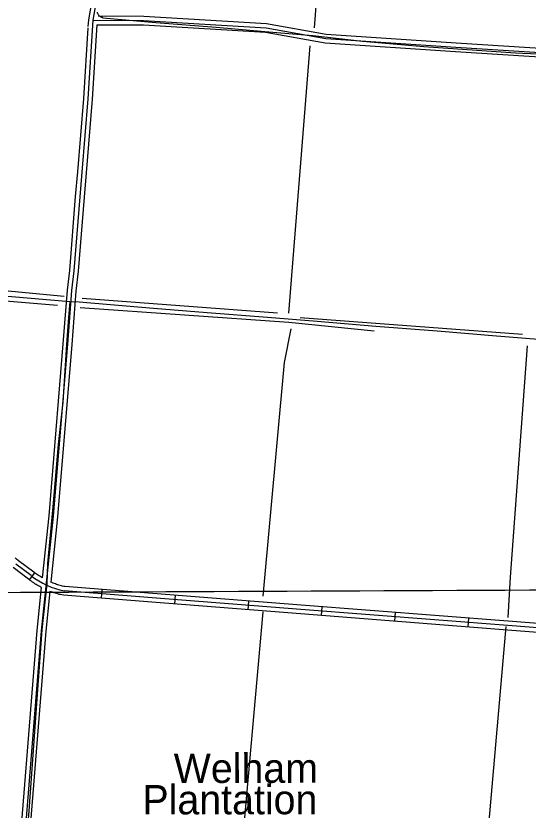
# Model space of a CAD drawing. Extents: x 3419139 to 3457078, y 540382 to 565875.
# Drawn here: x 3450842 to 3452584, y 551211 to 553912 of the extents above; entities that cross this region are included whole.
import ezdxf

# ---------------------------------------------------------------- set-up
doc = ezdxf.new("R2010")
doc.units = 0
for name, color, linetype in [('V-BLDG-IDEN', 7, 'Continuous'), ('V-DTCH-CNTR', 7, 'Continuous'), ('V-GRID-MAJR', 7, 'Continuous'), ('V-RAIL-TRAK', 7, 'Continuous'), ('V-ROAD-CNTR', 7, 'Continuous'), ('V-TOPO-SHOR', 7, 'Continuous')]:
    doc.layers.add(name, color=color, linetype=linetype)

msp = doc.modelspace()

# ---------------------------------------------------------------- linework, layer by layer
at = {"layer": 'V-DTCH-CNTR'}
for points in [[(3451138.4, 553905.2), (3451136.4, 553905.7), (3451134.3, 553906.3), (3451132.3, 553907.2), (3451130.5, 553908.2), (3451128.7, 553909.4), (3451127, 553910.7), (3451125.5, 553912.2), (3451124.1, 553913.9), (3451122.9, 553915.6), (3451121.8, 553917.5), (3451121, 553919.4), (3451120.3, 553921.5), (3451119.8, 553923.6), (3451119.6, 553924.7)], [(3451138.4, 553905.2), (3451317.8, 553889.8), (3451523.1, 553872.9), (3451688.3, 553858.3), (3451852.5, 553844.7), (3452021.1, 553826.2), (3452229.3, 553807.3), (3452541.5, 553786.3), (3452667.6, 553780.2), (3452893.1, 553767.5), (3453165, 553743), (3453421.6, 553726.2), (3453578.6, 553709.2), (3453645.5, 553697.3), (3453682.3, 553691.1), (3453726.5, 553689.1)], [(3451025.2, 552940.1), (3451020.7, 552885.8), (3451014.2, 552794.5), (3451001.4, 552598.6), (3450985.6, 552454.3), (3450968.3, 552242.3), (3450950, 552049.8), (3450947.1, 551980.6)], [(3450947.1, 551980.6), (3450930.6, 551824.6), (3450911.7, 551558), (3450886.9, 551208.2), (3450869.2, 551008.3)]]:
    msp.add_lwpolyline(points, dxfattribs=at)
at = {"layer": 'V-GRID-MAJR'}
msp.add_spline([(3423248.5, 551833.1), (3428523.1, 551854.2), (3433797.7, 551876), (3439072.3, 551898.7), (3444346.9, 551922.1), (3449621.5, 551946.2), (3454896.1, 551971.2)], degree=3, dxfattribs=at)
at = {"layer": 'V-RAIL-TRAK'}
msp.add_lwpolyline([(3452689.8, 552805.5), (3452476.7, 552822.8), (3452275, 552839.5), (3452065.8, 552856.1), (3451866.4, 552872.2), (3451698.4, 552885.8), (3451492.5, 552902.6), (3451309.8, 552917.4), (3451057.1, 552938), (3451025.2, 552940.1), (3450894.4, 552951.1), (3450705.8, 552967)], dxfattribs=at)
at = {"layer": 'V-ROAD-CNTR'}
for p, q in [((3450888.1, 551994.6), (3450906.5, 552018.4)), ((3451133.8, 551931.6), (3451136.2, 551961.5)), ((3451383, 551911.9), (3451385.4, 551941.8)), ((3451632.3, 551892.2), (3451634.6, 551922.2)), ((3451881.5, 551872.7), (3451883.8, 551902.6)), ((3452130.8, 551853.4), (3452133.1, 551883.4)), ((3452380, 551834.2), (3452382.4, 551864.1))]:
    msp.add_line(p, q, dxfattribs=at)
for points in [[(3451361.9, 556878.3), (3451369.7, 556800), (3451362.6, 556687.6), (3451325, 556203), (3451310, 556034.4), (3451302.3, 555964.6), (3451282.2, 555870.9), (3451228.2, 555310.1), (3451201.8, 554986), (3451160.5, 554477.3), (3451121.6, 553997), (3451115.6, 553961.6), (3451103.7, 553896.8), (3451086.8, 553629.9), (3451066.8, 553379.9), (3451059.4, 553296.4), (3451039.7, 553044.9), (3451031.5, 552977.6), (3451017.3, 552795.4), (3450968.8, 552210.3), (3450928.7, 551821.3), (3450867.5, 551057.2)], [(3451348, 556865.7), (3451354.6, 556799.7), (3451347.7, 556688.6), (3451310.1, 556204.2), (3451295.1, 556035.9), (3451287.4, 555967), (3451267.4, 555873.1), (3451213.2, 555311.4), (3451186.9, 554987.2), (3451145.6, 554478.5), (3451106.7, 553998.9), (3451100.9, 553964.2), (3451088.8, 553898.7), (3451087.3, 553875.6)], [(3451121.7, 553911.7), (3451277, 553910.9), (3451695, 553885.8), (3451897.6, 553850), (3452338.8, 553820.6), (3452661.1, 553800), (3453088.4, 553772.4), (3453429.7, 553742.7), (3453578.1, 553728.8), (3453669.2, 553700.5), (3453706.2, 553662.9)], [(3451117.8, 553881.8), (3451101.7, 553628.8), (3451081.8, 553378.7), (3451074.3, 553295.1), (3451054.6, 553043.4), (3451046.4, 552976.1), (3451032.2, 552794.2), (3450983.8, 552208.9), (3450960.8, 551986.4)], [(3451103.7, 553896.8), (3451276.5, 553895.9), (3451693.2, 553870.9), (3451895.8, 553835.1), (3452337.8, 553805.6), (3452660.1, 553785), (3453087.3, 553757.5), (3453428.3, 553727.8), (3453575.1, 553714), (3453661.2, 553687.3), (3453707.9, 553639.7)], [(3451117.8, 553881.8), (3451276, 553880.9), (3451691.5, 553856), (3451894, 553820.1), (3452336.8, 553790.6), (3452659.1, 553770), (3453086.2, 553742.5), (3453427, 553712.9), (3453572.2, 553699.2), (3453653.1, 553674.1), (3453691.9, 553634.6)], [(3451087, 553871), (3451071.8, 553630.9), (3451051.9, 553381.2), (3451044.4, 553297.6), (3451024.7, 553046.4), (3451016.6, 552979.1), (3451002.3, 552796.6), (3450953.9, 552211.6), (3450932.2, 552000.9)], [(3450932.2, 552000.9), (3450930.4, 552001.9), (3450926.7, 552004.2), (3450923.2, 552006.4), (3450919.6, 552008.8), (3450916.1, 552011.2), (3450912.7, 552013.7), (3450909.2, 552016.2), (3450905.8, 552018.9), (3450903.8, 552020.5), (3450851.6, 552059.3), (3450849, 552061.5), (3450846, 552063.9), (3450843.1, 552066.2), (3450840, 552068.5)], [(3450894.6, 552008.6), (3450842.3, 552047.6)], [(3450928.8, 551968.4), (3450927.4, 551969.2), (3450923.2, 551971.4), (3450919, 551973.8), (3450914.9, 551976.2), (3450910.8, 551978.7), (3450906.8, 551981.3), (3450902.8, 551984), (3450898.9, 551986.7), (3450895, 551989.5), (3450891.1, 551992.3), (3450887.4, 551995.2), (3450885.5, 551996.7), (3450833, 552035.8)], [(3450928.8, 551968.4), (3450913.8, 551822.7), (3450852.5, 551058.4), (3450810, 550513.6), (3450781, 550125.6), (3450733.2, 549557.6), (3450728.9, 549537.9), (3450723.2, 549531.5), (3450717.5, 549526.6), (3450695, 549519.3), (3450140.9, 549536.4)], [(3453414.6, 551783.9), (3452516.4, 551853.7), (3451811.9, 551908.2), (3451307.4, 551947.9), (3451008.7, 551971.6), (3451005.3, 551972.3), (3451001.2, 551973.2), (3450997.1, 551974.3), (3450992.9, 551975.3), (3450988.8, 551976.5), (3450984.7, 551977.7), (3450980.6, 551979), (3450976.6, 551980.3), (3450972.6, 551981.7), (3450968.6, 551983.2), (3450964.7, 551984.8), (3450960.8, 551986.4)], [(3450957.6, 551955.3), (3450943.6, 551819.9), (3450882.4, 551056), (3450839.9, 550511.3), (3450810.9, 550123.3), (3450762.9, 549553.1), (3450756.5, 549523.7), (3450744.2, 549510), (3450732.4, 549499.9), (3450699.3, 549489.1), (3450138.9, 549506.5)], [(3453411.6, 551754.1), (3452514, 551823.8), (3451809.6, 551878.3), (3451305, 551918), (3451004.6, 551941.9), (3450999.1, 551943), (3450994.4, 551944), (3450989.8, 551945.1), (3450985.1, 551946.3), (3450980.5, 551947.6), (3450976, 551949), (3450971.4, 551950.4), (3450966.8, 551952), (3450962.3, 551953.6), (3450957.6, 551955.3)], [(3453428, 551767.8), (3452515.2, 551838.8), (3451810.7, 551893.2), (3451306.2, 551933), (3451006.7, 551956.7)]]:
    msp.add_lwpolyline(points, dxfattribs=at)
msp.add_arc((3451056.4, 552211.1), 259.2, 231.3945, 258.9439, dxfattribs=at)
at = {"layer": 'V-TOPO-SHOR'}
for p, q in [((3451858, 553870.7), (3451930.1, 554848.2)), ((3451770.6, 552900.8), (3451843, 553809.6)), ((3450388.3, 553017), (3451007, 552958.6)), ((3450380.9, 552978.8), (3450984.2, 552927.9)), ((3451732.4, 552900.7), (3451068.1, 552951.2)), ((3452564.9, 552828), (3451808.8, 552885.7)), ((3451552.4, 550426.5), (3451683.4, 551885.1)), ((3452508.1, 551835.3), (3452362.7, 550162.8))]:
    msp.add_line(p, q, dxfattribs=at)
for points in [[(3451060.6, 552920.6), (3451770.7, 552870.3), (3452061, 552841)], [(3451683.2, 551938.6), (3451756.1, 552732.8), (3451778.5, 552847.4)], [(3452580.3, 552789.9), (3452522.7, 552003.3), (3452515.6, 551865.9)]]:
    msp.add_lwpolyline(points, dxfattribs=at)

# ---------------------------------------------------------------- texts
at = {"layer": 'V-BLDG-IDEN'}
for s, p in [('Welham', (3451379.1, 551303.6)), ('Plantation', (3451272.7, 551196.7))]:
    msp.add_text(s, height=100, rotation=0.088, dxfattribs=at).set_placement(p)

doc.saveas('drawing.dxf')
